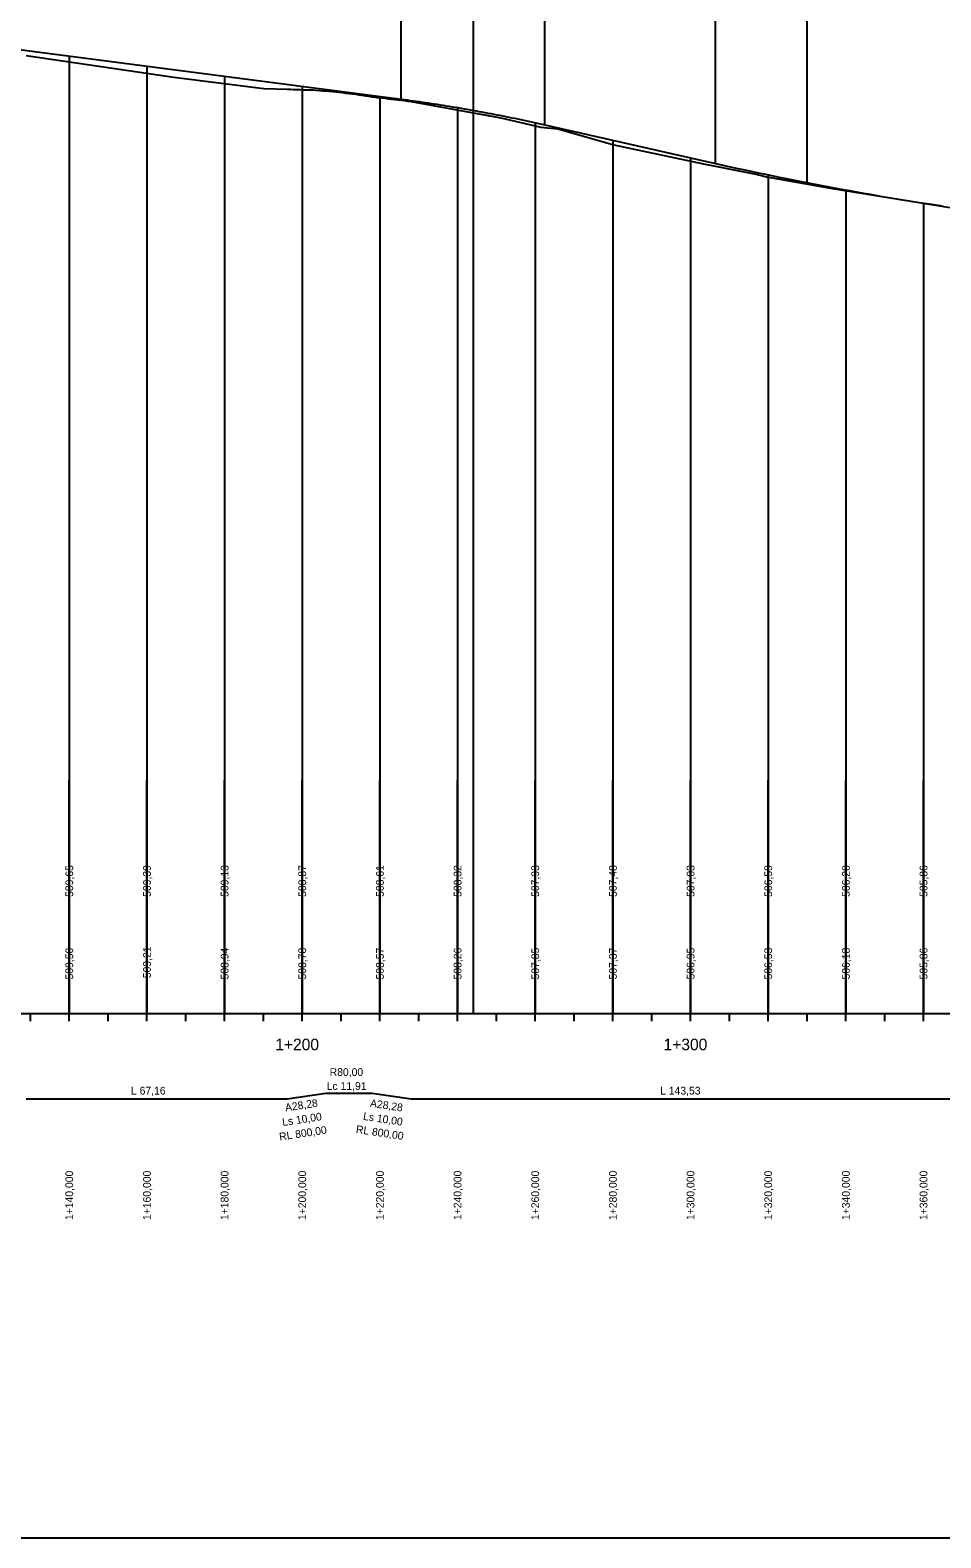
# Model space of a CAD drawing. Extents: x -632716 to -629545, y -1094726 to -1088285.
# Drawn here: x -631398.7 to -631164.2, y -1091981 to -1091592.8 of the extents above; entities that cross this region are included whole.
import ezdxf

# ---------------------------------------------------------------- set-up
doc = ezdxf.new("R2010")
doc.units = 0
for name, color, linetype in [('20', 7, 'Continuous'), ('Default', 7, 'Continuous'), ('formát', 7, 'Continuous'), ('NIVELETA_VYSKY', 7, 'Continuous'), ('REZ_POPIS', 7, 'Continuous'), ('REZ_TABULKA', 7, 'Continuous'), ('REZ_TENKA', 7, 'Continuous'), ('REZ_TLUSTA', 7, 'Continuous'), ('SKLONY_NIVELETA', 7, 'Continuous'), ('TECNY_NIVELETA', 7, 'Continuous'), ('TEREN_VYSKY', 7, 'Continuous'), ('VOZOVKA', 7, 'Continuous')]:
    doc.layers.add(name, color=color, linetype=linetype)

msp = doc.modelspace()

# ---------------------------------------------------------------- linework, layer by layer
at = {"layer": '20'}
for points in [[(-631388.64, -1091599.5), (-631388.64, -1091795.99), (-631388.64, -1091845.99), (-631388.64, -1091785.99)], [(-631368.64, -1091602.1), (-631368.64, -1091795.99), (-631368.64, -1091845.99), (-631368.64, -1091785.99)], [(-631348.64, -1091604.7), (-631348.64, -1091795.99), (-631348.64, -1091845.99), (-631348.64, -1091785.99)], [(-631328.64, -1091607.3), (-631328.64, -1091795.99), (-631328.64, -1091845.99), (-631328.64, -1091785.99)], [(-631308.64, -1091609.9), (-631308.64, -1091795.99), (-631308.64, -1091845.99), (-631308.64, -1091785.99)], [(-631288.64, -1091612.77), (-631288.64, -1091795.99), (-631288.64, -1091845.99), (-631288.64, -1091785.99)], [(-631268.64, -1091616.65), (-631268.64, -1091795.99), (-631268.64, -1091845.99), (-631268.64, -1091785.99)], [(-631248.64, -1091621.17), (-631248.64, -1091795.99), (-631248.64, -1091845.99), (-631248.64, -1091785.99)], [(-631228.64, -1091625.69), (-631228.64, -1091795.99), (-631228.64, -1091845.99), (-631228.64, -1091785.99)], [(-631208.64, -1091630.09), (-631208.64, -1091795.99), (-631208.64, -1091845.99), (-631208.64, -1091785.99)], [(-631188.64, -1091633.99), (-631188.64, -1091795.99), (-631188.64, -1091845.99), (-631188.64, -1091785.99)], [(-631168.64, -1091637.35), (-631168.64, -1091795.99), (-631168.64, -1091845.99), (-631168.64, -1091785.99)]]:
    msp.add_lwpolyline(points, dxfattribs=at)
at = {"layer": 'Default'}
for p, q in [((-631420.67, -1091595.33), (-631303.16, -1091610.61)), ((-631266.17, -1091617.2), (-631222.18, -1091627.15))]:
    msp.add_line(p, q, dxfattribs=at)
for points in [[(-631303.16, -1091610.61), (-631302.39, -1091610.71), (-631301.62, -1091610.82), (-631300.85, -1091610.92), (-631300.08, -1091611.03), (-631299.31, -1091611.13), (-631298.53, -1091611.24), (-631297.76, -1091611.35), (-631296.99, -1091611.46), (-631296.22, -1091611.58), (-631295.45, -1091611.69), (-631294.68, -1091611.81), (-631293.91, -1091611.93), (-631293.14, -1091612.05), (-631292.37, -1091612.17), (-631291.6, -1091612.29), (-631290.83, -1091612.41), (-631290.06, -1091612.54), (-631289.29, -1091612.67), (-631288.52, -1091612.79), (-631287.75, -1091612.92), (-631286.98, -1091613.06), (-631286.21, -1091613.19), (-631285.44, -1091613.32), (-631283.89, -1091613.6), (-631283.12, -1091613.74), (-631282.35, -1091613.88), (-631281.58, -1091614.02), (-631280.81, -1091614.17), (-631280.04, -1091614.31), (-631279.27, -1091614.46), (-631278.5, -1091614.61), (-631277.73, -1091614.76), (-631276.96, -1091614.91), (-631276.19, -1091615.06), (-631275.42, -1091615.22), (-631274.65, -1091615.38), (-631273.88, -1091615.53), (-631273.11, -1091615.69), (-631272.34, -1091615.85), (-631271.57, -1091616.02), (-631270.8, -1091616.18), (-631270.02, -1091616.35), (-631269.25, -1091616.51), (-631268.48, -1091616.68), (-631267.71, -1091616.85), (-631266.94, -1091617.03), (-631266.17, -1091617.2)], [(-631222.18, -1091627.15), (-631219.53, -1091627.74), (-631216.88, -1091628.33), (-631214.23, -1091628.91), (-631211.58, -1091629.47), (-631208.93, -1091630.03), (-631206.28, -1091630.58), (-631203.63, -1091631.12), (-631200.98, -1091631.65), (-631198.32, -1091632.17), (-631195.67, -1091632.68), (-631193.02, -1091633.18), (-631190.37, -1091633.67), (-631187.72, -1091634.15), (-631185.07, -1091634.63), (-631182.42, -1091635.09), (-631179.77, -1091635.54), (-631177.12, -1091635.99), (-631174.47, -1091636.42), (-631171.82, -1091636.85), (-631169.17, -1091637.27), (-631166.52, -1091637.67), (-631163.86, -1091638.07)]]:
    msp.add_lwpolyline(points, dxfattribs=at)
at = {"layer": 'formát'}
msp.add_lwpolyline([(-632628.81, -1091981.01), (-629779.11, -1091981.01), (-629779.11, -1091387.01), (-632628.81, -1091387.01)], close=True, dxfattribs=at)
at = {"layer": 'REZ_TABULKA'}
msp.add_lwpolyline([(-631399.7, -1091867.99), (-631332.53, -1091867.99), (-631332.53, -1091867.99), (-631322.53, -1091866.49), (-631322.53, -1091866.49), (-631310.62, -1091866.49), (-631310.62, -1091866.49), (-631300.62, -1091867.99), (-631300.62, -1091867.99), (-631157.09, -1091867.99), (-631157.09, -1091868.47), (-631114.51, -1091868.47), (-631114.51, -1091867.99), (-631012.48, -1091867.99), (-631012.48, -1091868.47), (-630989.49, -1091868.47), (-630989.49, -1091867.99), (-630908.74, -1091867.99)], dxfattribs=at)
at = {"layer": 'REZ_TENKA'}
for p, q in [((-631398.64, -1091847.99), (-631398.64, -1091845.99)), ((-631388.64, -1091847.99), (-631388.64, -1091845.99)), ((-631378.64, -1091847.99), (-631378.64, -1091845.99)), ((-631368.64, -1091847.99), (-631368.64, -1091845.99)), ((-631358.64, -1091847.99), (-631358.64, -1091845.99)), ((-631348.64, -1091847.99), (-631348.64, -1091845.99)), ((-631338.64, -1091847.99), (-631338.64, -1091845.99)), ((-631318.64, -1091847.99), (-631318.64, -1091845.99)), ((-631308.64, -1091847.99), (-631308.64, -1091845.99)), ((-631298.64, -1091847.99), (-631298.64, -1091845.99)), ((-631288.64, -1091847.99), (-631288.64, -1091845.99)), ((-631278.64, -1091847.99), (-631278.64, -1091845.99)), ((-631268.64, -1091847.99), (-631268.64, -1091845.99)), ((-631258.64, -1091847.99), (-631258.64, -1091845.99)), ((-631248.64, -1091847.99), (-631248.64, -1091845.99)), ((-631238.64, -1091847.99), (-631238.64, -1091845.99)), ((-631218.64, -1091847.99), (-631218.64, -1091845.99)), ((-631208.64, -1091847.99), (-631208.64, -1091845.99)), ((-631198.64, -1091847.99), (-631198.64, -1091845.99)), ((-631188.64, -1091847.99), (-631188.64, -1091845.99)), ((-631178.64, -1091847.99), (-631178.64, -1091845.99)), ((-631168.64, -1091847.99), (-631168.64, -1091845.99))]:
    msp.add_line(p, q, dxfattribs=at)
at = {"layer": 'REZ_TLUSTA'}
for p, q in [((-632528.64, -1091845.99), (-630208.64, -1091845.99)), ((-631328.64, -1091847.99), (-631328.64, -1091843.99)), ((-631228.64, -1091847.99), (-631228.64, -1091843.99))]:
    msp.add_line(p, q, dxfattribs=at)
at = {"layer": 'SKLONY_NIVELETA'}
for p, q in [((-631284.66, -1091513.02), (-631284.66, -1091845.99)), ((-631420.67, -1091595.33), (-631303.16, -1091610.61)), ((-631266.17, -1091617.2), (-631222.18, -1091627.15))]:
    msp.add_line(p, q, dxfattribs=at)
for points in [[(-631303.16, -1091610.61), (-631302.39, -1091610.71), (-631301.62, -1091610.82), (-631300.85, -1091610.92), (-631300.08, -1091611.03), (-631299.31, -1091611.13), (-631298.53, -1091611.24), (-631297.76, -1091611.35), (-631296.99, -1091611.46), (-631296.22, -1091611.58), (-631295.45, -1091611.69), (-631294.68, -1091611.81), (-631293.91, -1091611.93), (-631293.14, -1091612.05), (-631292.37, -1091612.17), (-631291.6, -1091612.29), (-631290.83, -1091612.41), (-631290.06, -1091612.54), (-631289.29, -1091612.67), (-631288.52, -1091612.79), (-631287.75, -1091612.92), (-631286.98, -1091613.06), (-631286.21, -1091613.19), (-631285.44, -1091613.32), (-631283.89, -1091613.6), (-631283.12, -1091613.74), (-631282.35, -1091613.88), (-631281.58, -1091614.02), (-631280.81, -1091614.17), (-631280.04, -1091614.31), (-631279.27, -1091614.46), (-631278.5, -1091614.61), (-631277.73, -1091614.76), (-631276.96, -1091614.91), (-631276.19, -1091615.06), (-631275.42, -1091615.22), (-631274.65, -1091615.38), (-631273.88, -1091615.53), (-631273.11, -1091615.69), (-631272.34, -1091615.85), (-631271.57, -1091616.02), (-631270.8, -1091616.18), (-631270.02, -1091616.35), (-631269.25, -1091616.51), (-631268.48, -1091616.68), (-631267.71, -1091616.85), (-631266.94, -1091617.03), (-631266.17, -1091617.2)], [(-631222.18, -1091627.15), (-631219.53, -1091627.74), (-631216.88, -1091628.33), (-631214.23, -1091628.91), (-631211.58, -1091629.47), (-631208.93, -1091630.03), (-631206.28, -1091630.58), (-631203.63, -1091631.12), (-631200.98, -1091631.65), (-631198.32, -1091632.17), (-631195.67, -1091632.68), (-631193.02, -1091633.18), (-631190.37, -1091633.67), (-631187.72, -1091634.15), (-631185.07, -1091634.63), (-631182.42, -1091635.09), (-631179.77, -1091635.54), (-631177.12, -1091635.99), (-631174.47, -1091636.42), (-631171.82, -1091636.85), (-631169.17, -1091637.27), (-631166.52, -1091637.67), (-631163.86, -1091638.07)]]:
    msp.add_lwpolyline(points, dxfattribs=at)
at = {"layer": 'TECNY_NIVELETA'}
for p, q in [((-631198.64, -1091632.11), (-631198.64, -1091466.32)), ((-631303.16, -1091610.61), (-631303.16, -1091509.61)), ((-631266.17, -1091617.2), (-631266.17, -1091516.2)), ((-631222.18, -1091627.15), (-631222.18, -1091526.15))]:
    msp.add_line(p, q, dxfattribs=at)
at = {"layer": 'VOZOVKA'}
msp.add_lwpolyline([(-631399.7, -1091599.37), (-631361.71, -1091604.91), (-631338.56, -1091607.85), (-631332.53, -1091608.04), (-631331.7, -1091608.07), (-631330.87, -1091608.09), (-631330.03, -1091608.12), (-631329.2, -1091608.14), (-631328.37, -1091608.17), (-631327.53, -1091608.19), (-631326.7, -1091608.21), (-631325.87, -1091608.23), (-631325.86, -1091608.23), (-631325.03, -1091608.3), (-631324.2, -1091608.36), (-631323.37, -1091608.43), (-631322.53, -1091608.49), (-631321.68, -1091608.56), (-631320.83, -1091608.62), (-631319.98, -1091608.68), (-631319.72, -1091608.7), (-631319.13, -1091608.78), (-631318.28, -1091608.9), (-631317.43, -1091609.02), (-631316.58, -1091609.13), (-631315.73, -1091609.25), (-631314.88, -1091609.36), (-631314.03, -1091609.47), (-631313.38, -1091609.56), (-631313.17, -1091609.59), (-631312.32, -1091609.72), (-631311.47, -1091609.85), (-631310.62, -1091609.97), (-631309.79, -1091610.1), (-631309.45, -1091610.15), (-631308.95, -1091610.2), (-631308.12, -1091610.3), (-631307.29, -1091610.39), (-631306.45, -1091610.48), (-631305.62, -1091610.57), (-631304.79, -1091610.67), (-631303.95, -1091610.76), (-631303.12, -1091610.85), (-631302.31, -1091610.94), (-631302.29, -1091610.94), (-631301.45, -1091611.09), (-631300.62, -1091611.24), (-631277.53, -1091615.38), (-631267.24, -1091617.81), (-631262.83, -1091618.27), (-631248.4, -1091622.33), (-631225.28, -1091627.24), (-631211.39, -1091629.98), (-631209.11, -1091630.62), (-631192.58, -1091633.55), (-631160.77, -1091638.67)], dxfattribs=at)

# ---------------------------------------------------------------- texts
at = {"layer": 'NIVELETA_VYSKY'}
for s, p in [('509,65', (-631387.64, -1091815.99)), ('509,39', (-631367.64, -1091815.99)), ('509,13', (-631347.64, -1091815.99)), ('508,87', (-631327.64, -1091815.99)), ('508,61', (-631307.64, -1091815.99)), ('508,32', (-631287.64, -1091815.99)), ('507,93', (-631267.64, -1091815.99)), ('507,48', (-631247.64, -1091815.99)), ('507,03', (-631227.64, -1091815.99)), ('506,59', (-631207.64, -1091815.99)), ('506,20', (-631187.64, -1091815.99)), ('505,86', (-631167.64, -1091815.99))]:
    msp.add_text(s, height=2, rotation=90, dxfattribs=at).set_placement(p)
at = {"layer": 'REZ_POPIS'}
for s, p in [('1+200', (-631335.59, -1091855.49)), ('1+300', (-631235.59, -1091855.49))]:
    msp.add_text(s, height=3, dxfattribs=at).set_placement(p)
at = {"layer": 'REZ_TABULKA'}
for s, p in [('R80,00', (-631321.58, -1091862.09)), ('L 67,16', (-631372.75, -1091866.88)), ('Lc 11,91', (-631322.34, -1091865.69)), ('L 143,53', (-631236.48, -1091866.88))]:
    msp.add_text(s, height=2, dxfattribs=at).set_placement(p)
for s, rotation, p in [('A28,28', 8.5308, (-631332.91, -1091871.24)), ('A28,28', 351.4692, (-631311.27, -1091870.01)), ('Ls 10,00', 8.5308, (-631333.65, -1091874.99)), ('Ls 10,00', 351.4692, (-631313.07, -1091873.38)), ('RL 800,00', 8.5308, (-631334.43, -1091878.75)), ('RL 800,00', 351.4692, (-631314.92, -1091876.74)), ('1+140,000', 90, (-631387.64, -1091899.2)), ('1+160,000', 90, (-631367.64, -1091899.2)), ('1+180,000', 90, (-631347.64, -1091899.2)), ('1+200,000', 90, (-631327.64, -1091899.2)), ('1+220,000', 90, (-631307.64, -1091899.2)), ('1+240,000', 90, (-631287.64, -1091899.2)), ('1+260,000', 90, (-631267.64, -1091899.2)), ('1+280,000', 90, (-631247.64, -1091899.2)), ('1+300,000', 90, (-631227.64, -1091899.2)), ('1+320,000', 90, (-631207.64, -1091899.2)), ('1+340,000', 90, (-631187.64, -1091899.2)), ('1+360,000', 90, (-631167.64, -1091899.2))]:
    msp.add_text(s, height=2, rotation=rotation, dxfattribs=at).set_placement(p)
at = {"layer": 'TEREN_VYSKY'}
for s, p in [('509,50', (-631387.64, -1091837.25)), ('509,21', (-631367.64, -1091836.92)), ('508,94', (-631347.64, -1091837.25)), ('508,78', (-631327.64, -1091837.25)), ('508,57', (-631307.64, -1091837.25)), ('508,26', (-631287.64, -1091837.25)), ('507,85', (-631267.64, -1091837.25)), ('507,37', (-631247.64, -1091837.25)), ('506,95', (-631227.64, -1091837.25)), ('506,53', (-631207.64, -1091837.25)), ('506,18', (-631187.64, -1091837.25)), ('505,86', (-631167.64, -1091837.25))]:
    msp.add_text(s, height=2, rotation=90, dxfattribs=at).set_placement(p)

doc.saveas('drawing.dxf')
